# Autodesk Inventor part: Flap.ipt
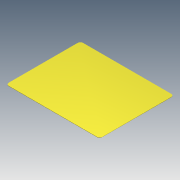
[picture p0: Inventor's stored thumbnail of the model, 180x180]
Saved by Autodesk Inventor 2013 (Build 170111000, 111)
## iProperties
Created: 2005-05
Part Number: Flap.ipt
Material: Steel, Mild
Document SubType Name: Modeling
Designer: PVitaliy
Manufacturer: Standard
Standards Organization: Custom
Density: 1 g/cm^3
Author: PVitaliy
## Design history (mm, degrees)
sketch "Эскиз2"
  geometry: L1 (0, 0)-(680, 0); L2 (680, 0)-(680, 540); L3 (680, 540)-(0, 540); L4 (0, 540)-(0, 0)
  constraints: 8 end point, 2 parallel, 1 horizontal, 1 perpendicular, 1 other
  dimensions: "d0" = 680 distance of L1.start L1.end; "d1" = 540 distance of L3.end L1.start
extrude "Выдавливание1" new body sketch "Эскиз2" distance "d2" = 2; taper "d3" = 0 deg
fillet "Сопряжение1" dims "d4" = 20
body "Solid1"
